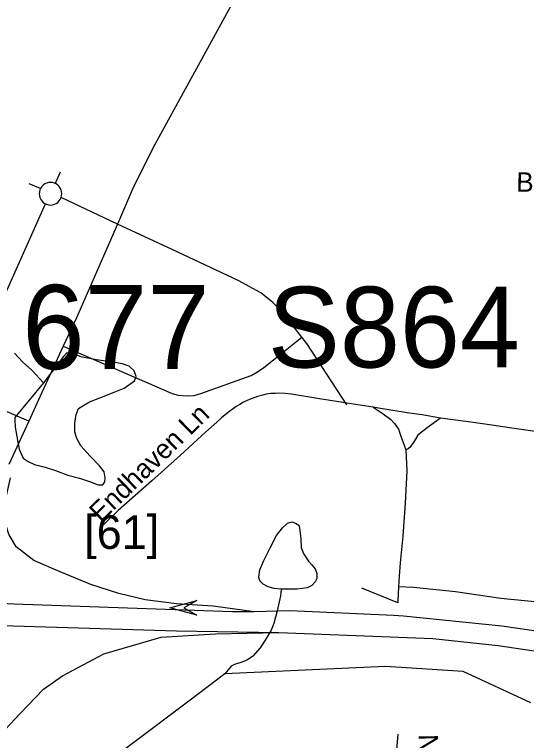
# Model space of a CAD drawing. Extents: x 1383679 to 1536984, y 460658 to 651027.
# Drawn here: x 1448113 to 1450610, y 483158 to 486697 of the extents above; entities that cross this region are included whole.
import ezdxf

# ---------------------------------------------------------------- set-up
doc = ezdxf.new("R2010")
doc.units = 0
for name, color, linetype in [('Exist Hydrographic Creek Single Shore', 7, 'Continuous'), ('Exist Hydrographic Misc Water Feature', 7, 'Continuous'), ('Exist Road Non-System Type 51', 7, 'Continuous'), ('Exist Road Non-System Type 51 Label', 7, 'Continuous'), ('Exist Road Primary Interstate Divided Center Attributed', 7, 'Continuous'), ('Exist Road Primary Interstate Ramp 1 Lane Attributed', 7, 'Continuous'), ('Exist Road Primary Interstate Shield CELL', 7, 'Continuous'), ('Exist Road Primary Interstate Structure Ovrhead Sign Attributed CELL', 7, 'Continuous'), ('Exist Road Primary Interstate Structure Ovrhead Sign Number Label', 7, 'Continuous'), ('Exist Road Secondary Structure Standard Bridge Number Label', 7, 'Continuous')]:
    doc.layers.add(name, color=color, linetype=linetype)

msp = doc.modelspace()

# ---------------------------------------------------------------- linework, layer by layer
at = {"layer": 'Exist Hydrographic Creek Single Shore'}
msp.add_lwpolyline([(1450631, 483341.9), (1450302.2, 483494.8), (1449922.4, 483518.4), (1449139, 483483.5), (1448970, 483355.2), (1448382.2, 482913), (1447997.1, 482655.5), (1447799, 482673.6), (1447552.4, 482785.6), (1447330.1, 482896.2), (1447225.8, 482956.7), (1446831, 483120.2), (1446515, 483238.6), (1446352.4, 483568.7), (1446248.7, 483809.2), (1446066, 484021), (1445953.2, 484107.5), (1445854.2, 484158.7)], dxfattribs=at)
at = {"layer": 'Exist Hydrographic Misc Water Feature'}
for points in [[(1448113, 485045.3), (1448152.2, 485004.3), (1448197.5, 484963.1), (1448254.5, 484902.1)], [(1448254.5, 484902.1), (1448115.2, 484732.6), (1448115, 484721.1), (1448116.4, 484684.9), (1448127.3, 484622.3), (1448136.5, 484578.7), (1448155.6, 484534), (1448179.3, 484517.9), (1448211.2, 484503.3), (1448262.9, 484490), (1448312.6, 484473.4), (1448374.2, 484451.6), (1448429.9, 484436.6), (1448483.6, 484418.3), (1448521.3, 484403.6), (1448543.5, 484404.7), (1448553.7, 484418.5), (1448556.2, 484438.9), (1448550.6, 484467), (1448527.2, 484497), (1448482, 484543.8), (1448437, 484594.8), (1448417.5, 484629.7), (1448408, 484661.1), (1448406.9, 484705.3), (1448413.6, 484747.1), (1448426.2, 484775.6), (1448446.5, 484789.1), (1448478.8, 484808.1), (1448529.2, 484827.7), (1448599.8, 484855.8), (1448648.2, 484875.3), (1448698.8, 484910.4), (1448707.1, 484932.4), (1448697.7, 484960.5), (1448672.1, 484983.1), (1448640.3, 484993.6), (1448592.4, 485002), (1448512.5, 485013.4), (1448442.8, 485027.1), (1448393.1, 485043.7), (1448369.1, 485048.3), (1448352.7, 485029), (1448254.5, 484902.1)], [(1449414.5, 483894.8), (1449380.6, 483899.6), (1449350.8, 483907.6), (1449326.9, 483920.4), (1449309.2, 483936.3), (1449305.6, 483954.5), (1449310.3, 483990.5), (1449329, 484036.1), (1449360.2, 484097.8), (1449391.3, 484157.1), (1449420.1, 484195.1), (1449444.5, 484216.8), (1449466.6, 484223.7), (1449484.5, 484217.6), (1449500.3, 484207.4), (1449504.1, 484193.4), (1449509.1, 484140.8), (1449512.3, 484097.2), (1449523.7, 484066.6), (1449547.1, 484032.5), (1449562.8, 484014.1), (1449580.4, 483994.1), (1449588.1, 483971.8), (1449587.6, 483948), (1449579.3, 483931.7), (1449562.9, 483914), (1449540.8, 483902.2), (1449492.6, 483894.9), (1449448.6, 483895.8), (1449414.5, 483894.8)], [(1449414.5, 483894.8), (1449409.9, 483862.9), (1449394.7, 483789.4), (1449377.5, 483729), (1449364.8, 483695.6), (1449336, 483647.8), (1449311.3, 483608.9), (1449276.5, 483569.4), (1449250.2, 483551.9), (1449222, 483540.1), (1449185.8, 483528.6), (1449169.6, 483520.7), (1449155.3, 483502.9), (1449139, 483483.5)]]:
    msp.add_lwpolyline(points, dxfattribs=at)
at = {"layer": 'Exist Road Non-System Type 51'}
for p, q in [((1448336.4, 485928.9), (1448311.9, 485873.4)), ((1448240.1, 485848.3), (1448184.4, 485871.8)), ((1448615.1, 485675.3), (1448341.1, 485805.2)), ((1448182.9, 484714.7), (1448067, 484765.7)), ((1448182.9, 484714.7), (1448086.2, 484504.1)), ((1449983.3, 483828.2), (1449807.5, 483901))]:
    msp.add_line(p, q, dxfattribs=at)
for points in [[(1448905.2, 488009.3), (1448928.8, 487991.2), (1448973.2, 487949.8), (1449043.4, 487888.2), (1449109.8, 487807.2), (1449161.9, 487729), (1449209.8, 487655.1), (1449240.1, 487583.3), (1449268.4, 487509.5), (1449290.1, 487439.9), (1449316.9, 487334.2), (1449319.9, 487242.2), (1449311.1, 487128.7), (1449302.4, 487064.7), (1449276.2, 486968.6), (1449238.4, 486881.3), (1449174.4, 486750.3), (1448797.1, 486063), (1448693.4, 485857.5), (1448615.1, 485675.3)], [(1448311.9, 485873.4), (1448307.9, 485875), (1448298.6, 485877.5), (1448289.1, 485878.3), (1448279.5, 485877.5), (1448270.2, 485875), (1448261.6, 485871), (1448253.8, 485865.5), (1448247, 485858.7), (1448241.5, 485850.8), (1448240.1, 485848.3)], [(1448341.1, 485805.2), (1448343.2, 485813.8), (1448344.1, 485823.3), (1448343.2, 485832.9), (1448340.8, 485842.1), (1448336.8, 485850.8), (1448331.2, 485858.7), (1448324.5, 485865.5), (1448316.6, 485871), (1448311.9, 485873.4)], [(1448240.1, 485848.3), (1448237.4, 485842.1), (1448234.9, 485832.8), (1448234, 485823.3), (1448234.9, 485813.7), (1448237.4, 485804.5), (1448241.4, 485795.8), (1448246.9, 485787.9), (1448253.8, 485781.1), (1448261.5, 485775.6), (1448264.2, 485774.2)], [(1448264.2, 485774.2), (1448270.2, 485771.6), (1448279.5, 485769.1), (1448289.1, 485768.2), (1448298.6, 485769.1), (1448307.9, 485771.6), (1448316.6, 485775.6), (1448324.5, 485781.1), (1448331.2, 485787.9), (1448336.8, 485795.8), (1448339.6, 485801.4), (1448341.1, 485805.2)], [(1447980.2, 485138.2), (1447995.5, 485172.1), (1448264.2, 485774.2)], [(1448615.1, 485675.3), (1448415.1, 485218.8), (1448351.4, 485080.8)], [(1449515.5, 485124.1), (1449422.5, 485243.2), (1449373.6, 485293.3), (1449314.1, 485340.1), (1449203.5, 485400.8), (1448882.4, 485550.7), (1448615.1, 485675.3)], [(1448351.4, 485080.8), (1448882, 484849.7), (1448911, 484841.7), (1448956, 484838.7), (1448989, 484839.7), (1449022, 484848.7), (1449267, 484936.7), (1449299, 484954.7), (1449329, 484976.7), (1449418, 485046.7), (1449515.5, 485124.1)], [(1449733.8, 484794.2), (1449538.9, 485093.9), (1449515.5, 485124.1)], [(1448351.4, 485080.8), (1448247.4, 484854.9), (1448182.9, 484714.7)], [(1449862.1, 484782.5), (1449788.3, 484793.9), (1449704.7, 484807.8), (1449600.6, 484824.2), (1449512.6, 484837.8), (1449464.3, 484845.6), (1449432.8, 484849.2), (1449403.3, 484850.4), (1449386.1, 484850), (1449363.9, 484848.7), (1449341, 484845.5), (1449325.3, 484841.9), (1449299.3, 484834.8), (1449272.1, 484825.7), (1449251.2, 484816.9), (1449229.8, 484806.4), (1449212.3, 484796.4), (1449195.2, 484785.7), (1449181, 484776.2), (1449163.3, 484763.4), (1449149.4, 484751.7), (1449123.2, 484730.1), (1449099.8, 484709.2), (1449044.9, 484660.9), (1448922.2, 484548.8), (1448782.6, 484423.2), (1448619.4, 484279.6), (1448566.9, 484228), (1448550.1, 484212.6), (1448529.1, 484189)], [(1450190.8, 484729.9), (1450101.4, 484744.7), (1450075, 484748.5), (1450027.8, 484755.2), (1449948.7, 484768), (1449889.3, 484778.3), (1449862.1, 484782.5)], [(1449862.1, 484782.5), (1449911.9, 484750.3), (1449948.1, 484722), (1449966.8, 484702.7), (1449985.4, 484675.5), (1449997.1, 484641.5), (1450014.6, 484597.3), (1450021.6, 484574.7)], [(1450190.8, 484729.9), (1450126.8, 484682.3), (1450081.2, 484646.1), (1450063.7, 484618.9), (1450043.8, 484588.3), (1450033.3, 484579.2), (1450021.6, 484574.7)], [(1451277.5, 484541.8), (1451192.8, 484557.1), (1451096.9, 484574.4), (1450982.9, 484598.1), (1450859.4, 484618.9), (1450777, 484644.2), (1450675.7, 484660.1), (1450539.3, 484680), (1450440.8, 484694.3), (1450338.6, 484709), (1450226.3, 484724.1), (1450190.8, 484729.9)], [(1450021.6, 484574.7), (1450027.5, 484472.7), (1450018.7, 484314.1), (1450007, 484153.2), (1449994.8, 484024), (1449988.9, 483959.4), (1449986.6, 483907.3)], [(1451405.3, 484510.4), (1451318, 484292.5), (1451249.1, 484086.3), (1451139.9, 483800.8), (1451118.3, 483766.8), (1451101.9, 483757.7), (1451086.8, 483752), (1451068.1, 483753.2), (1451027.2, 483761.1), (1450917.4, 483789.4), (1450797.1, 483811), (1450716, 483826.8), (1450484.7, 483850.6), (1450263.4, 483882.4), (1450059, 483903.9), (1449986.6, 483907.3)], [(1449986.6, 483907.3), (1449983.7, 483839.3), (1449983.3, 483828.2)], [(1450749.7, 480014.5), (1450698.7, 480224.9), (1450673.3, 480467.1), (1450628.7, 480734.9), (1450590.4, 480919.8), (1450501.3, 481155.6), (1450367.5, 481410.6), (1450233.7, 481665.6), (1450138.1, 481869.6), (1450042.6, 482086.4), (1449978.9, 482328.6), (1449953.4, 482577.3), (1449953.4, 482832.3), (1449985.2, 483189.3)]]:
    msp.add_lwpolyline(points, dxfattribs=at)
at = {"layer": 'Exist Road Primary Interstate Divided Center Attributed'}
for points in [[(1449281.9, 483785.1), (1449176.5, 483785.1), (1448942.1, 483792.9), (1448110.7, 483822.9), (1448047.9, 483826.5), (1448003.7, 483827.7), (1447822.2, 483829.1)], [(1455058.1, 483174.1), (1454856.2, 483163), (1454669.9, 483156.3), (1454250.6, 483127.5), (1453955.4, 483118.4), (1453391.7, 483122.5), (1452990.4, 483167.3), (1452697.6, 483220.6), (1452247.2, 483318.2), (1451136.4, 483601.3), (1450902.3, 483655.9), (1450490.8, 483714.5), (1450011.1, 483764.3), (1449962, 483766.7), (1449456.7, 483790), (1449281.9, 483785.1)], [(1447756, 483720.4), (1447992.2, 483720.5), (1448106.4, 483716.3), (1448903.2, 483692.9), (1449402.8, 483684.6)], [(1449402.8, 483684.6), (1450153.6, 483654.6), (1450473.1, 483621.3), (1450812.5, 483570.2), (1451083.2, 483516.9), (1452194, 483238.3), (1452637.7, 483140.6), (1452937.2, 483087.4), (1453292.1, 483038.5), (1453656, 483018.5), (1454006.6, 483018.7), (1454303.8, 483032), (1454694.3, 483047.6), (1454913.9, 483056.4), (1455135.8, 483072)]]:
    msp.add_lwpolyline(points, dxfattribs=at)
at = {"layer": 'Exist Road Primary Interstate Ramp 1 Lane Attributed'}
for points in [[(1449281.9, 483785.1), (1449082.7, 483812.5), (1448903, 483824.2), (1448750.6, 483843.7), (1448621.7, 483875), (1448485, 483918), (1448336.5, 483980.6), (1448207.6, 484035.3), (1448121.7, 484101.8), (1448086.5, 484164.3), (1448063.1, 484234.7), (1448070.9, 484336.4), (1448094.3, 484438)], [(1446701.2, 481343.7), (1446835.6, 481622.9), (1446935.1, 481820.1), (1446996.8, 481925.6), (1447086.3, 482039.1), (1447163.6, 482153.4), (1447207.4, 482207.2), (1447292.4, 482307.9), (1447442.2, 482474.1), (1447560, 482602.5), (1447726.4, 482788.6), (1447883.7, 482979.3), (1448021.3, 483162.5), (1448141.1, 483289.7), (1448254.8, 483407.8), (1448347.2, 483473.6), (1448548.3, 483580.7), (1448828.8, 483661.9), (1449093.1, 483678.1), (1449402.8, 483684.6)]]:
    msp.add_lwpolyline(points, dxfattribs=at)
at = {"layer": 'Exist Road Primary Interstate Structure Ovrhead Sign Attributed CELL'}
msp.add_lwpolyline([(1449003.2, 483769.6), (1448870.7, 483805.1), (1449003.2, 483840.6), (1448939.3, 483805.1)], close=True, dxfattribs=at)

# ---------------------------------------------------------------- texts
at = {"layer": 'Exist Road Non-System Type 51 Label'}
for s, rotation, p in [('Barrette Pl', 358.9957, (1450559.9, 485833.4)), ('Endhaven Ln', 44.214, (1448534.6, 484217.7)), ('North Community House Rd', 271.1577, (1450084, 483187.9))]:
    msp.add_text(s, height=95, rotation=rotation, dxfattribs=at).set_placement(p)
at = {"layer": 'Exist Road Primary Interstate Shield CELL'}
msp.add_text('[61]', height=164.04, dxfattribs=at).set_placement((1448453.3, 484091.7))
at = {"layer": 'Exist Road Primary Interstate Structure Ovrhead Sign Number Label'}
msp.add_text('S864', height=393.7, dxfattribs=at).set_placement((1449349.1, 484976.2))
at = {"layer": 'Exist Road Secondary Structure Standard Bridge Number Label'}
msp.add_text('677', height=410.1, dxfattribs=at).set_placement((1448150.5, 484968.5))

doc.saveas('drawing.dxf')
